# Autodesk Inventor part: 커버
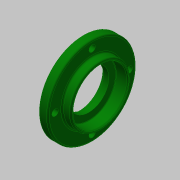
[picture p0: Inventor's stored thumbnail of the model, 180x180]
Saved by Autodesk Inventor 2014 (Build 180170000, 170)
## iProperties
Created: 2018-11
Part Number: 커버
Material: 알루미늄 6061
Document SubType Name: Modeling
Designer: mduedu
Density: 1 g/cm^3
Appearance: 진녹색
Author: mduedu
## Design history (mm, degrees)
sketch "스케치1"
  geometry: L1 (0, 0)-(3, 0); L2 (3, 0)-(3, 20); L3 (3, 20)-(0, 20); L4 (0, 20)-(0, 0); L5 (3, 0)-(9, 0); L6 (9, 0)-(9, 31); L7 (9, 31)-(3, 31); L8 (3, 31)-(3, 0); L9 (9, 0)-(15, 0); L10 (15, 0)-(15, 21); L11 (15, 21)-(9, 21); L12 (9, 21)-(9, 0)
  constraints: 24 end point, 6 parallel, 3 horizontal, 3 perpendicular
  dimensions: "d0" = 62 diameter of L7 L5; "d2" = 42 diameter of L11 L9; "d3" = 40 diameter of L3 L1; "d4" = 3 distance of L2.end L3.end; "d5" = 6 distance of L6.end L7.end; "d6" = 15 distance between parallel lines of L10 L4
revolve "회전1" sketch "스케치1" stored, may be unused: angle "d7" = 90 deg
sketch "스케치2"
  geometry: L1 (0, -20)-(0, 20) reference; L2 (0, 20)-(3, 20) reference; L3 (3, 20)-(3, 31) reference; L4 (3, 31)-(9, 31) reference; L5 (9, 31)-(9, 21) reference; L6 (9, 21)-(15, 21) reference; L7 (15, 21)-(15, -21) reference; L8 (15, -21)-(9, -21) reference; L9 (9, -21)-(9, -31) reference; L10 (9, -31)-(3, -31) reference; L11 (3, -31)-(3, -20) reference; L12 (3, -20)-(0, -20) reference; L13 (0, 0)-(3, 0); L14 (3, 0)-(3, 16.5); L15 (3, 16.5)-(0, 16.5); L16 (0, 16.5)-(0, 0); L17 (3, 0)-(6.7, 0); L18 (6.7, 0)-(6.7, 14); L19 (6.7, 14)-(3, 14); L20 (3, 14)-(3, 0); L21 (6.7, 0)-(15, 0); L22 (15, 0)-(15, 19); L23 (15, 19)-(6.7, 19); L24 (6.7, 19)-(6.7, 0)
  constraints: 24 end point, 6 parallel, 3 horizontal, 3 perpendicular, 1 point on line
  dimensions: "d8" = 38 diameter of L23 L21; "d10" = 28 diameter of L19 L17; "d11" = 33 diameter of L15 L13; "d12" = 3 distance of L14.end L15.end; "d13" = 8.3 distance of L22.end L23.end
revolve "회전2" sketch "스케치2" stored, may be unused: angle "d14" = 90 deg
fillet "모깎기1" dims "d15" = 0.3
chamfer "모따기1" distance "d16" = 0.8; stored, may be unused: second distance "d17" = 2, angle "d18" = 30 deg
fillet "모깎기2" dims "d19" = 1
chamfer "모따기2" distance "d20" = 0.5; stored, may be unused: second distance "d21" = 2, angle "d22" = 30 deg
sketch "스케치3" dims "d23" = 52
  geometry: 6 further points
  constraints: 2 vertical alignment, 1 coincident, 7 other
  dimensions: "d26" = 360 deg dimension on point (0, 0) point (0, 26) (derived)
sketch "스케치4"
  geometry: 4 further points
  constraints: 4 other
hole "구멍1" sketch "스케치4" at (-26, 0), (0, -26), (26, 0), (0, 26) diameter "d28" = 4.5; stored, may be unused: countersink angle "d32" = 90 deg, drill point angle "d34" = 0 deg; dims "d29" = 6, "d30" = 8, "d31" = 4.6, "d33" = 8
node "솔리드1"
node "절단 모서리 투영1"
